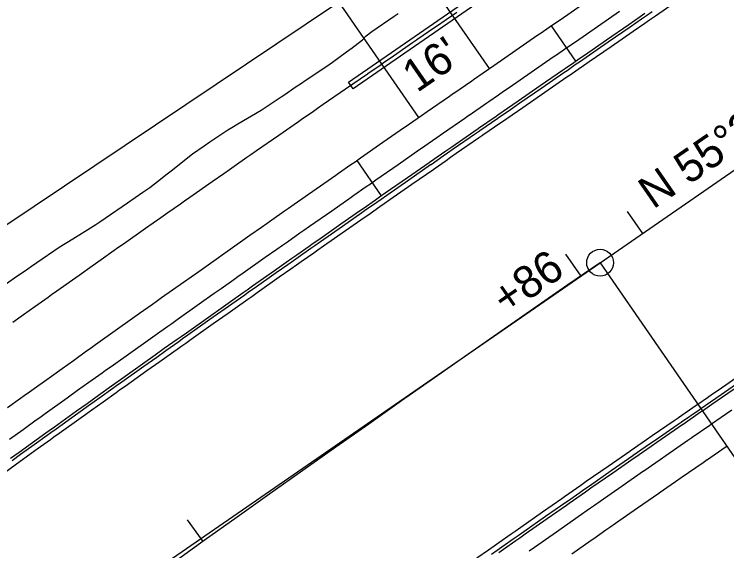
# Model space of a CAD drawing. Extents: x 1147550 to 1149124, y 2017436 to 2018779.
# Drawn here: x 1148099.8 to 1148232.5, y 2017914.6 to 2018014.6 of the extents above; entities that cross this region are included whole.
import ezdxf

# ---------------------------------------------------------------- set-up
doc = ezdxf.new("R2010")
doc.units = 0
for name, color, linetype in [('S_EDGE_CONCRETE', 7, 'Continuous'), ('S_HEADWALL', 7, 'Continuous'), ('S_MAILBOX', 7, 'Continuous'), ('S_RDW_PT_SYM', 7, 'Continuous'), ('S_SECONDARY_CTL', 7, 'Continuous'), ('S_TELEPHONE_UTILITIES', 7, 'Continuous'), ('S_TELEPHONE_UTILITIES_ANNOT', 7, 'Continuous'), ('S_UTL_PT_SYM', 7, 'Continuous')]:
    doc.layers.add(name, color=color, linetype=linetype)

msp = doc.modelspace()

# ---------------------------------------------------------------- linework, layer by layer
at = {"layer": 'S_EDGE_CONCRETE'}
for p, q in [((1148208.89, 2017968.31), (1148293.22, 2018026.54)), ((1148011.14, 2017831.73), (1148208.89, 2017968.31))]:
    msp.add_line(p, q, dxfattribs=at)
for points in [[(1148213.95, 2017977.88), (1148216.79, 2017973.76)], [(1148132.01, 2017920.42), (1148134.91, 2017916.35)]]:
    msp.add_lwpolyline(points, dxfattribs=at)
msp.add_circle((1148208.89, 2017968.31), 2.5, dxfattribs=at)
msp.add_arc((1151464.82, 2013253.76), 5729.58, 124.62946, 129.43332, dxfattribs=at)
at = {"layer": 'S_HEADWALL'}
for p, q in [((1148173.48, 2018025.83), (1148188.24, 2018004.48)), ((1148160.19, 2018016.91), (1148175.09, 2017995.38)), ((1148199.76, 2018012.44), (1148204.31, 2018005.86)), ((1148163.59, 2017987.38), (1148168.14, 2017980.8)), ((1148202.43, 2017969.92), (1148205.27, 2017965.8))]:
    msp.add_line(p, q, dxfattribs=at)
at = {"layer": 'S_MAILBOX'}
msp.add_lwpolyline([(1147550.1, 2017525.89), (1147894.72, 2017801.4), (1147903.55, 2017831.14), (1148035.64, 2017933.4), (1148261.5, 2018084.85), (1148285.74, 2018084.65), (1148479.1, 2018223.18), (1148835.76, 2018573.62)], dxfattribs=at)
at = {"layer": 'S_RDW_PT_SYM'}
msp.add_lwpolyline([(1148208.89, 2017968.31), (1148277.08, 2017869.57)], dxfattribs=at)
at = {"layer": 'S_SECONDARY_CTL'}
msp.add_lwpolyline([(1148097.69, 2017964), (1148099.83, 2017965.48), (1148102.31, 2017967.19), (1148102.98, 2017967.65), (1148103.99, 2017968.34), (1148108.17, 2017971.18), (1148110.67, 2017972.75), (1148112.46, 2017973.87), (1148114.97, 2017975.43), (1148115.7, 2017975.91), (1148116.71, 2017976.6), (1148120.88, 2017979.46), (1148123.72, 2017981.43), (1148125.04, 2017982.34), (1148127.34, 2017984.11), (1148128.04, 2017984.66), (1148129.03, 2017985.44), (1148133, 2017988.57), (1148135.15, 2017990.11), (1148136.23, 2017990.85), (1148137.14, 2017991.47), (1148139.53, 2017993.06), (1148140.31, 2017993.52), (1148141.41, 2017994.18), (1148145.78, 2017996.76), (1148149.5, 2017999.2), (1148149.99, 2017999.54), (1148152.31, 2018001.13), (1148153.1, 2018001.66), (1148154.17, 2018002.38), (1148158.36, 2018005.2), (1148162.37, 2018008.12), (1148162.45, 2018008.18), (1148164.62, 2018009.86), (1148165.35, 2018010.56), (1148166.36, 2018011.39), (1148170.54, 2018014.23), (1148171.31, 2018014.76)], dxfattribs=at)
at = {"layer": 'S_TELEPHONE_UTILITIES'}
for points in [[(1148095.89, 2017927.74), (1148099.97, 2017930.67), (1148101.54, 2017931.81), (1148104.05, 2017933.61), (1148106.51, 2017935.37), (1148107.17, 2017935.84), (1148108.14, 2017936.54), (1148112.23, 2017939.47), (1148114.21, 2017940.88), (1148116.32, 2017942.39), (1148118.76, 2017944.13), (1148119.41, 2017944.6), (1148120.41, 2017945.31), (1148124.5, 2017948.23), (1148126.9, 2017949.93), (1148128.6, 2017951.14), (1148131, 2017952.84), (1148131.71, 2017953.34), (1148132.7, 2017954.05), (1148136.81, 2017956.96), (1148139.61, 2017958.94), (1148140.91, 2017959.86), (1148143.28, 2017961.53), (1148144, 2017962.04), (1148145.02, 2017962.76), (1148149.13, 2017965.65), (1148151.28, 2017967.17), (1148152.35, 2017967.92), (1148153.24, 2017968.54), (1148155.58, 2017970.18), (1148156.32, 2017970.7), (1148157.36, 2017971.43), (1148161.48, 2017974.32), (1148165.11, 2017976.86), (1148165.6, 2017977.2), (1148167.89, 2017978.8), (1148168.67, 2017979.34), (1148169.72, 2017980.08), (1148173.85, 2017982.95), (1148177.9, 2017985.77), (1148177.98, 2017985.82), (1148180.22, 2017987.38), (1148181.04, 2017987.95), (1148182.11, 2017988.69), (1148186.24, 2017991.55), (1148187, 2017992.08), (1148187.07, 2017992.12), (1148190.38, 2017994.41), (1148190.71, 2017994.64), (1148192.5, 2017995.87), (1148193.48, 2017996.55), (1148194.49, 2017997.25), (1148198.61, 2018000.09), (1148202.72, 2018002.93), (1148203.3, 2018003.33), (1148204.83, 2018004.39), (1148205.8, 2018005.06), (1148206.83, 2018005.77), (1148210.95, 2018008.62), (1148215.06, 2018011.46), (1148217.19, 2018012.93), (1148218.09, 2018013.55), (1148219.18, 2018014.3), (1148223.29, 2018017.14)], [(1148098.51, 2017941.32), (1148100.97, 2017943.09), (1148101.63, 2017943.56), (1148102.6, 2017944.26), (1148106.7, 2017947.19), (1148108.68, 2017948.61), (1148110.8, 2017950.12), (1148113.24, 2017951.87), (1148113.9, 2017952.34), (1148114.89, 2017953.05), (1148119, 2017955.97), (1148121.39, 2017957.67), (1148123.1, 2017958.89), (1148125.5, 2017960.59), (1148126.21, 2017961.09), (1148127.21, 2017961.8), (1148131.32, 2017964.71), (1148134.13, 2017966.7), (1148135.43, 2017967.62), (1148137.8, 2017969.29), (1148138.52, 2017969.8), (1148139.55, 2017970.52), (1148143.66, 2017973.42), (1148145.82, 2017974.94), (1148146.89, 2017975.69), (1148147.78, 2017976.32), (1148150.12, 2017977.96), (1148150.86, 2017978.48), (1148151.91, 2017979.21), (1148156.03, 2017982.1), (1148159.67, 2017984.65), (1148160.16, 2017984.99), (1148162.45, 2017986.59), (1148163.24, 2017987.13), (1148164.29, 2017987.87), (1148168.42, 2017990.75), (1148172.48, 2017993.57), (1148172.56, 2017993.62), (1148174.81, 2017995.18), (1148175.63, 2017995.75), (1148176.69, 2017996.49), (1148180.83, 2017999.36), (1148181.6, 2017999.89), (1148181.66, 2017999.93), (1148184.98, 2018002.22), (1148185.31, 2018002.45), (1148187.1, 2018003.69), (1148188.08, 2018004.37), (1148189.09, 2018005.07), (1148193.21, 2018007.91), (1148197.32, 2018010.75), (1148197.9, 2018011.15), (1148199.43, 2018012.21), (1148200.41, 2018012.88), (1148201.44, 2018013.59), (1148205.55, 2018016.43)], [(1148098.92, 2017935.46), (1148101.43, 2017937.26), (1148103.89, 2017939.03), (1148104.54, 2017939.5), (1148105.52, 2017940.2), (1148109.61, 2017943.13), (1148111.59, 2017944.55), (1148113.7, 2017946.05), (1148116.14, 2017947.79), (1148116.8, 2017948.26), (1148117.8, 2017948.98), (1148121.9, 2017951.89), (1148124.29, 2017953.6), (1148126, 2017954.81), (1148128.39, 2017956.51), (1148129.1, 2017957.01), (1148130.1, 2017957.72), (1148134.21, 2017960.63), (1148137.01, 2017962.61), (1148138.32, 2017963.53), (1148140.68, 2017965.21), (1148141.41, 2017965.72), (1148142.43, 2017966.44), (1148146.54, 2017969.33), (1148148.69, 2017970.85), (1148149.76, 2017971.6), (1148150.66, 2017972.23), (1148152.99, 2017973.87), (1148153.73, 2017974.39), (1148154.78, 2017975.12), (1148158.9, 2017978), (1148162.53, 2017980.55), (1148163.02, 2017980.89), (1148165.32, 2017982.49), (1148166.1, 2017983.03), (1148167.15, 2017983.77), (1148171.28, 2017986.64), (1148175.33, 2017989.46), (1148175.41, 2017989.52), (1148177.66, 2017991.08), (1148178.47, 2017991.64), (1148179.54, 2017992.38), (1148183.68, 2017995.25), (1148184.44, 2017995.78), (1148184.51, 2017995.82), (1148187.82, 2017998.11), (1148188.15, 2017998.34), (1148189.94, 2017999.58), (1148190.92, 2018000.25), (1148191.93, 2018000.95), (1148196.05, 2018003.79), (1148200.16, 2018006.64), (1148200.74, 2018007.03), (1148202.27, 2018008.09), (1148203.25, 2018008.77), (1148204.28, 2018009.48), (1148208.39, 2018012.32), (1148212.51, 2018015.16)], [(1148099.09, 2017931.89), (1148100.67, 2017933.02), (1148103.18, 2017934.83), (1148105.64, 2017936.59), (1148106.29, 2017937.06), (1148107.26, 2017937.76), (1148111.35, 2017940.69), (1148113.34, 2017942.1), (1148115.44, 2017943.61), (1148117.88, 2017945.35), (1148118.54, 2017945.82), (1148119.54, 2017946.53), (1148123.64, 2017949.45), (1148126.03, 2017951.15), (1148127.73, 2017952.36), (1148130.13, 2017954.06), (1148130.84, 2017954.57), (1148131.84, 2017955.27), (1148135.94, 2017958.18), (1148138.75, 2017960.16), (1148140.05, 2017961.08), (1148142.41, 2017962.75), (1148143.14, 2017963.26), (1148144.16, 2017963.98), (1148148.27, 2017966.88), (1148150.42, 2017968.39), (1148151.49, 2017969.14), (1148152.38, 2017969.77), (1148154.72, 2017971.41), (1148155.46, 2017971.93), (1148156.5, 2017972.66), (1148160.62, 2017975.55), (1148164.25, 2017978.09), (1148164.74, 2017978.43), (1148167.03, 2017980.03), (1148167.81, 2017980.57), (1148168.86, 2017981.31), (1148172.99, 2017984.18), (1148177.04, 2017987), (1148177.12, 2017987.05), (1148179.37, 2017988.61), (1148180.18, 2017989.18), (1148181.25, 2017989.92), (1148185.39, 2017992.78), (1148186.15, 2017993.31), (1148186.21, 2017993.35), (1148189.52, 2017995.64), (1148189.86, 2017995.87), (1148191.65, 2017997.11), (1148192.63, 2017997.79), (1148193.64, 2017998.48), (1148197.75, 2018001.33), (1148201.87, 2018004.17), (1148202.44, 2018004.57), (1148203.97, 2018005.62), (1148204.95, 2018006.3), (1148205.98, 2018007.01), (1148210.1, 2018009.85), (1148214.21, 2018012.69), (1148216.34, 2018014.16), (1148217.24, 2018014.78)], [(1148099.39, 2017931.49), (1148100.96, 2017932.62), (1148103.47, 2017934.42), (1148105.93, 2017936.18), (1148106.58, 2017936.65), (1148107.56, 2017937.35), (1148111.64, 2017940.28), (1148113.63, 2017941.7), (1148115.74, 2017943.2), (1148118.17, 2017944.95), (1148118.83, 2017945.42), (1148119.83, 2017946.13), (1148123.92, 2017949.04), (1148126.32, 2017950.74), (1148128.02, 2017951.96), (1148130.42, 2017953.66), (1148131.13, 2017954.16), (1148132.12, 2017954.87), (1148136.23, 2017957.77), (1148139.03, 2017959.76), (1148140.33, 2017960.68), (1148142.7, 2017962.35), (1148143.42, 2017962.86), (1148144.44, 2017963.57), (1148148.56, 2017966.47), (1148150.71, 2017967.98), (1148151.77, 2017968.73), (1148152.67, 2017969.36), (1148155, 2017971), (1148155.74, 2017971.52), (1148156.79, 2017972.25), (1148160.9, 2017975.14), (1148164.54, 2017977.68), (1148165.03, 2017978.02), (1148167.32, 2017979.62), (1148168.1, 2017980.16), (1148169.15, 2017980.9), (1148173.28, 2017983.77), (1148177.33, 2017986.59), (1148177.41, 2017986.64), (1148179.65, 2017988.2), (1148180.47, 2017988.77), (1148181.54, 2017989.51), (1148185.67, 2017992.37), (1148186.44, 2017992.9), (1148186.5, 2017992.94), (1148189.81, 2017995.23), (1148190.14, 2017995.46), (1148191.93, 2017996.7), (1148192.91, 2017997.37), (1148193.92, 2017998.07), (1148198.04, 2018000.91), (1148202.15, 2018003.76), (1148202.73, 2018004.15), (1148204.26, 2018005.21), (1148205.24, 2018005.89), (1148206.27, 2018006.6), (1148210.38, 2018009.44), (1148214.49, 2018012.28), (1148216.62, 2018013.75), (1148217.52, 2018014.37), (1148218.61, 2018015.12)], [(1148185.96, 2017913.31), (1148188.09, 2017914.81), (1148189.14, 2017915.55), (1148190.03, 2017916.17), (1148192.34, 2017917.79), (1148193.07, 2017918.31), (1148194.1, 2017919.03), (1148198.17, 2017921.88), (1148201.76, 2017924.39), (1148202.25, 2017924.73), (1148204.51, 2017926.31), (1148205.28, 2017926.85), (1148206.32, 2017927.58), (1148210.4, 2017930.42), (1148214.41, 2017933.2), (1148214.49, 2017933.26), (1148216.71, 2017934.8), (1148217.52, 2017935.36), (1148218.57, 2017936.09), (1148222.66, 2017938.92), (1148223.41, 2017939.44), (1148223.48, 2017939.49), (1148226.75, 2017941.75), (1148227.08, 2017941.98), (1148228.87, 2017943.21), (1148229.85, 2017943.89), (1148230.86, 2017944.59), (1148234.97, 2017947.43)], [(1148188.66, 2017913.99), (1148189.72, 2017914.73), (1148190.6, 2017915.35), (1148192.91, 2017916.97), (1148193.64, 2017917.49), (1148194.67, 2017918.21), (1148198.74, 2017921.06), (1148202.34, 2017923.57), (1148202.82, 2017923.91), (1148205.09, 2017925.49), (1148205.86, 2017926.03), (1148206.9, 2017926.75), (1148210.97, 2017929.6), (1148214.98, 2017932.38), (1148215.06, 2017932.43), (1148217.28, 2017933.98), (1148218.09, 2017934.54), (1148219.14, 2017935.27), (1148223.23, 2017938.1), (1148223.98, 2017938.62), (1148224.04, 2017938.66), (1148227.32, 2017940.93), (1148227.65, 2017941.15), (1148229.44, 2017942.39), (1148230.42, 2017943.07), (1148231.43, 2017943.77), (1148235.54, 2017946.61)], [(1148190.01, 2017914.32), (1148190.89, 2017914.94), (1148193.2, 2017916.57), (1148193.93, 2017917.08), (1148194.96, 2017917.8), (1148199.03, 2017920.65), (1148202.62, 2017923.16), (1148203.11, 2017923.5), (1148205.37, 2017925.08), (1148206.14, 2017925.62), (1148207.18, 2017926.34), (1148211.26, 2017929.19), (1148215.26, 2017931.97), (1148215.34, 2017932.02), (1148217.56, 2017933.57), (1148218.37, 2017934.13), (1148219.43, 2017934.86), (1148223.51, 2017937.69), (1148224.27, 2017938.21), (1148224.33, 2017938.25), (1148227.6, 2017940.51), (1148227.93, 2017940.74), (1148229.72, 2017941.98), (1148230.7, 2017942.66), (1148231.71, 2017943.35), (1148235.83, 2017946.2)], [(1148195.65, 2017914.62), (1148196.68, 2017915.34), (1148200.75, 2017918.19), (1148204.34, 2017920.7), (1148204.82, 2017921.04), (1148207.09, 2017922.62), (1148207.86, 2017923.16), (1148208.9, 2017923.88), (1148212.97, 2017926.72), (1148216.98, 2017929.51), (1148217.05, 2017929.56), (1148219.27, 2017931.1), (1148220.08, 2017931.66), (1148221.13, 2017932.39), (1148225.22, 2017935.22), (1148225.97, 2017935.74), (1148226.04, 2017935.79), (1148229.31, 2017938.05), (1148229.63, 2017938.27), (1148231.43, 2017939.51), (1148232.41, 2017940.19), (1148233.42, 2017940.89)], [(1148203.62, 2017914.1), (1148207.21, 2017916.61), (1148207.69, 2017916.94), (1148209.95, 2017918.52), (1148210.72, 2017919.06), (1148211.76, 2017919.78), (1148215.83, 2017922.62), (1148219.83, 2017925.4), (1148219.91, 2017925.45), (1148222.12, 2017926.99), (1148222.93, 2017927.55), (1148223.98, 2017928.28), (1148228.06, 2017931.11), (1148228.82, 2017931.63), (1148228.88, 2017931.67), (1148232.15, 2017933.93), (1148232.48, 2017934.16)]]:
    msp.add_lwpolyline(points, dxfattribs=at)
at = {"layer": 'S_TELEPHONE_UTILITIES_ANNOT'}
msp.add_lwpolyline([(1148162.02, 2018001.97), (1148186.69, 2018019.03), (1148187.54, 2018017.8), (1148162.87, 2018000.73)], close=True, dxfattribs=at)
at = {"layer": 'S_UTL_PT_SYM'}
msp.add_lwpolyline([(1148099.5, 2017957.25), (1148101.5, 2017958.67), (1148103.62, 2017960.17), (1148106.07, 2017961.92), (1148106.73, 2017962.38), (1148107.73, 2017963.09), (1148111.85, 2017966.01), (1148114.26, 2017967.71), (1148115.97, 2017968.92), (1148118.38, 2017970.62), (1148119.1, 2017971.12), (1148120.1, 2017971.83), (1148124.23, 2017974.73), (1148127.05, 2017976.72), (1148128.36, 2017977.64), (1148130.74, 2017979.31), (1148131.46, 2017979.81), (1148132.49, 2017980.53), (1148136.62, 2017983.43), (1148138.79, 2017984.94), (1148139.86, 2017985.69), (1148140.76, 2017986.32), (1148143.11, 2017987.96), (1148143.85, 2017988.47), (1148144.9, 2017989.2), (1148149.04, 2017992.09), (1148152.7, 2017994.63), (1148153.19, 2017994.97), (1148155.49, 2017996.57), (1148156.28, 2017997.11), (1148157.33, 2017997.84), (1148161.48, 2018000.71), (1148165.56, 2018003.53), (1148165.64, 2018003.58), (1148167.9, 2018005.14), (1148168.72, 2018005.71), (1148169.79, 2018006.45), (1148173.95, 2018009.31), (1148174.72, 2018009.84), (1148174.78, 2018009.88), (1148178.11, 2018012.17), (1148178.44, 2018012.4), (1148180.24, 2018013.63), (1148181.22, 2018014.3), (1148182.23, 2018015)], dxfattribs=at)

# ---------------------------------------------------------------- texts
at = {"layer": 'S_HEADWALL'}
for s, p in [("16'", (1148174.79, 2017999.88)), ('+86', (1148191.42, 2017958.41))]:
    msp.add_text(s, height=6, rotation=34.6735, dxfattribs=at).set_placement(p)
at = {"layer": 'S_RDW_PT_SYM'}
msp.add_text('N 55%%d22\'14" E', height=6, rotation=34.6295, dxfattribs=at).set_placement((1148218.77, 2017978.17))

doc.saveas('drawing.dxf')
